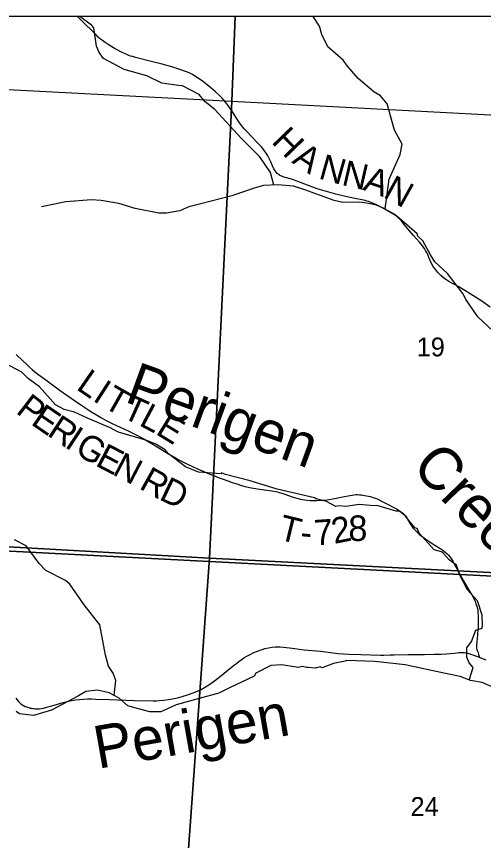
# Model space of a CAD drawing. Extents: x -2.1 to 31.9, y 6.3 to 28.3.
# Drawn here: x 1.092 to 2.128, y 25.414 to 27.244 of the extents above; entities that cross this region are included whole.
import ezdxf

# ---------------------------------------------------------------- set-up
doc = ezdxf.new("R2010")
doc.units = 0
for name, color, linetype in [('Default', 7, 'Continuous'), ('GM_X_County_Road', 7, 'Continuous'), ('GM_X_County_Road_Text', 7, 'Continuous'), ('GM_X_Minor_River', 7, 'Continuous'), ('GM_X_Minor_River_Text', 7, 'Continuous'), ('GM_X_Section', 7, 'Continuous'), ('GM_X_Section_Text', 7, 'Continuous'), ('GM_X_State_Route', 7, 'Continuous'), ('GM_X_Township_Road', 7, 'Continuous'), ('GM_X_Township_Road_Text', 7, 'Continuous'), ('SH_Cut_Line', 7, 'Continuous')]:
    doc.layers.add(name, color=color, linetype=linetype)

msp = doc.modelspace()

# ---------------------------------------------------------------- linework, layer by layer
at = {"layer": 'Default'}
msp.add_lwpolyline([(4.7331, 27.244), (0.0344, 27.244), (0.0344, 26.1105), (0.4641, 26.0883), (2.0757, 26.0047), (2.8034, 25.9683), (3.0763, 25.9555), (3.8625, 25.9158)], dxfattribs=at)
for points in [[(1.5768, 27.244), (0.5541, 27.244), (0.5464, 27.109), (1.5695, 27.0562)], [(2.6242, 27.244), (1.5768, 27.244), (1.5695, 27.0562), (2.6051, 27.0012), (2.6077, 27.001)], [(0.0344, 26.1105), (0.0344, 20.444), (3.7533, 20.444), (3.8489, 20.5389), (3.9894, 20.6326), (4.16, 20.7203), (4.2895, 20.7662), (4.3023, 20.7658), (4.3091, 20.8714), (4.3751, 21.8979), (4.4168, 22.5238), (4.4383, 22.8067), (4.4651, 23.2405), (4.4901, 23.6442), (4.5473, 24.5954), (4.5667, 24.9084), (4.6032, 25.4816), (4.6286, 25.8765), (3.8625, 25.9158), (3.0763, 25.9555), (2.8034, 25.9683), (2.0757, 26.0047), (0.4641, 26.0883)]]:
    msp.add_lwpolyline(points, close=True, dxfattribs=at)
at = {"layer": 'GM_X_County_Road'}
msp.add_lwpolyline([(2.1421, 26.5987), (2.1238, 26.6116), (2.1036, 26.6247), (2.0864, 26.6358), (2.079, 26.6401), (2.0725, 26.6437), (2.0659, 26.6472), (2.057, 26.6517), (2.0505, 26.6555), (2.0443, 26.6598), (2.0387, 26.664), (2.0333, 26.6686), (2.0294, 26.6723), (2.0262, 26.6756), (2.0217, 26.6812), (2.0185, 26.6857), (2.0163, 26.6888), (2.0125, 26.6953), (2.0093, 26.702), (2.0064, 26.709), (2.0038, 26.7153), (2.0011, 26.7208), (1.9989, 26.7246), (1.9964, 26.7286), (1.9937, 26.7324), (1.9898, 26.7373), (1.9854, 26.7425), (1.9722, 26.7578), (1.9554, 26.7779), (1.9494, 26.7854), (1.9448, 26.7909), (1.9394, 26.7963), (1.9336, 26.8014), (1.9293, 26.805), (1.9244, 26.808), (1.9176, 26.8119), (1.909, 26.8162), (1.8973, 26.8222), (1.8875, 26.8269), (1.8797, 26.8302), (1.8728, 26.8328), (1.8692, 26.834), (1.8653, 26.835), (1.8579, 26.8368), (1.8426, 26.8399), (1.8218, 26.8442), (1.8001, 26.8496), (1.7797, 26.855), (1.7688, 26.8583), (1.7586, 26.8615), (1.7371, 26.8696), (1.7162, 26.8778), (1.7088, 26.8804), (1.7019, 26.8826), (1.6879, 26.8865), (1.6831, 26.8882), (1.6785, 26.89), (1.6762, 26.8912), (1.6741, 26.8924), (1.6722, 26.8938), (1.6703, 26.8955), (1.6678, 26.8981), (1.6653, 26.9015), (1.6627, 26.9058), (1.6595, 26.9125), (1.6556, 26.921), (1.6515, 26.9299), (1.6492, 26.9345), (1.6469, 26.9384), (1.6441, 26.9427), (1.6415, 26.9464), (1.6384, 26.9505), (1.6353, 26.9543), (1.6275, 26.9628), (1.6148, 26.9758), (1.6044, 26.987), (1.5972, 26.9948), (1.592, 27.001), (1.5867, 27.0079), (1.5796, 27.0182), (1.5706, 27.0324), (1.5643, 27.042), (1.5594, 27.0491), (1.5557, 27.0538), (1.552, 27.058), (1.5479, 27.0624), (1.5412, 27.069), (1.5334, 27.0764), (1.5232, 27.0852), (1.5109, 27.0951), (1.5014, 27.1024), (1.493, 27.1081), (1.4874, 27.1117), (1.4824, 27.1148), (1.4763, 27.1178), (1.4709, 27.1202), (1.4646, 27.1229), (1.4585, 27.1251), (1.4519, 27.1273), (1.4361, 27.1321), (1.4149, 27.1381), (1.3934, 27.1435), (1.3559, 27.153), (1.3492, 27.1548), (1.345, 27.1561), (1.3411, 27.1575), (1.3369, 27.1592), (1.3326, 27.161), (1.3236, 27.1654), (1.317, 27.1688), (1.311, 27.1722), (1.3035, 27.1768), (1.2951, 27.1821), (1.2889, 27.1862), (1.2827, 27.1904), (1.2783, 27.1938), (1.2734, 27.1981), (1.2679, 27.2036), (1.2598, 27.2119), (1.2438, 27.2275), (1.2284, 27.2422), (1.2266, 27.244)], dxfattribs=at)
at = {"layer": 'GM_X_Minor_River'}
for points in [[(1.6629, 26.8693), (1.6555, 26.8976), (1.6316, 26.9326), (1.5905, 26.9737), (1.5319, 27.0375), (1.5105, 27.0545), (1.497, 27.0709), (1.4602, 27.0899), (1.4515, 27.0906), (1.4143, 27.096), (1.3811, 27.1122), (1.3305, 27.126), (1.2851, 27.1506), (1.2753, 27.1638), (1.2697, 27.1777), (1.2634, 27.2185), (1.2582, 27.2244), (1.2327, 27.244)], [(1.9093, 26.8167), (1.9185, 26.8829), (1.9424, 26.9372), (1.9469, 26.9606), (1.9305, 26.9919), (1.9141, 27.0497), (1.8995, 27.0681), (1.8847, 27.0769), (1.8493, 27.1065), (1.8263, 27.1338), (1.8165, 27.147), (1.7826, 27.1766), (1.7694, 27.2036), (1.7639, 27.2224), (1.7502, 27.244)], [(2.1487, 26.5451), (2.115, 26.5774), (2.0889, 26.6146), (2.082, 26.629), (2.0476, 26.673), (2.0196, 26.6992), (2.0101, 26.7147), (1.9927, 26.7459), (1.9817, 26.7565), (1.9806, 26.7614), (1.9409, 26.7963), (1.9363, 26.7997), (1.9049, 26.8186), (1.8902, 26.825), (1.8724, 26.8284), (1.8535, 26.8314), (1.8153, 26.8306), (1.7964, 26.8355), (1.7314, 26.8589), (1.706, 26.8672), (1.6713, 26.8705), (1.6395, 26.8685), (1.6187, 26.8628), (1.5696, 26.8459), (1.5004, 26.8278)], [(1.5006, 26.8279), (1.477, 26.8221), (1.4744, 26.8214), (1.4543, 26.8122), (1.4249, 26.8076), (1.4075, 26.8071), (1.3549, 26.8173), (1.319, 26.8286), (1.2797, 26.8353), (1.2581, 26.8368), (1.2011, 26.8321), (1.1474, 26.8213)], [(2.0958, 25.7706), (2.1044, 25.7985), (2.0957, 25.8087), (2.0904, 25.8217), (2.0908, 25.8418), (2.1006, 25.8559), (2.1108, 25.881), (2.1247, 25.886), (2.1251, 25.8924), (2.1247, 25.9145), (2.1141, 25.9464), (2.0922, 25.971), (2.0747, 26.0033), (2.0675, 26.0253), (2.0513, 26.0375), (2.038, 26.0522), (2.0342, 26.0553), (2.0184, 26.0594), (1.9847, 26.097), (1.9805, 26.1068), (1.9752, 26.1087), (1.954, 26.1353), (1.9412, 26.1455), (1.9336, 26.1459), (1.8939, 26.1572), (1.8761, 26.1583), (1.8515, 26.1605), (1.8221, 26.1562), (1.8066, 26.1573), (1.7998, 26.1558), (1.7793, 26.1668), (1.7563, 26.1732), (1.7525, 26.1751), (1.6697, 26.1946), (1.6103, 26.2127), (1.5551, 26.227), (1.5468, 26.2304), (1.546, 26.2282), (1.4958, 26.2322), (1.467, 26.2443), (1.4288, 26.2731), (1.422, 26.2818), (1.4012, 26.2943), (1.3808, 26.3023), (1.3184, 26.3207), (1.3048, 26.3275), (1.3033, 26.3294), (1.2496, 26.3521), (1.2204, 26.3653), (1.1977, 26.3714), (1.1785, 26.382), (1.1433, 26.4218), (1.1179, 26.4404), (1.1035, 26.454), (1.0544, 26.4801)], [(1.3088, 25.7363), (1.3122, 25.7695), (1.3067, 25.7856), (1.2962, 25.8011), (1.2894, 25.8256), (1.2771, 25.8932), (1.2421, 25.9376), (1.2106, 25.9834), (1.2003, 25.9918), (1.1571, 26.0136), (1.1425, 26.0297), (1.1138, 26.0686), (1.0877, 26.0819)], [(1.8244, 25.8142), (1.8209, 25.8126), (1.7948, 25.8072), (1.7699, 25.7977), (1.765, 25.7999), (1.754, 25.7973), (1.7385, 25.7987), (1.7347, 25.7987), (1.7264, 25.8006), (1.7166, 25.7987), (1.6807, 25.8043), (1.6557, 25.8031), (1.6225, 25.7855), (1.6191, 25.7794), (1.5643, 25.7534), (1.5409, 25.7412), (1.497, 25.7293), (1.446, 25.7155), (1.4124, 25.7002), (1.409, 25.7002), (1.3878, 25.7002), (1.3628, 25.7066), (1.3386, 25.7134), (1.3193, 25.7304), (1.2978, 25.7421), (1.2717, 25.7482), (1.246, 25.7454), (1.2294, 25.7359), (1.1693, 25.7038), (1.13, 25.6919), (1.099, 25.6957), (1.0914, 25.701)], [(2.1479, 25.7549), (2.1249, 25.7651), (2.0984, 25.7696), (2.0761, 25.7783), (2.0436, 25.7854), (1.954, 25.8046), (1.8863, 25.8116), (1.8244, 25.8142)]]:
    msp.add_lwpolyline(points, dxfattribs=at)
at = {"layer": 'GM_X_Section'}
for points in [[(0.5464, 27.109), (1.5695, 27.0562), (1.5197, 26.0415), (0.4693, 26.1002)], [(1.5695, 27.0562), (2.6051, 27.0012), (2.5466, 25.9887), (1.5197, 26.0415)], [(0.4693, 26.1002), (1.5197, 26.0415), (1.4457, 25.016), (0.4184, 25.0658)], [(1.5197, 26.0415), (2.5466, 25.9887), (2.4786, 24.9709), (1.4457, 25.016)]]:
    msp.add_lwpolyline(points, close=True, dxfattribs=at)
at = {"layer": 'GM_X_State_Route'}
msp.add_lwpolyline([(1.0907, 25.73), (1.0933, 25.7267), (1.0963, 25.7233), (1.099, 25.7205), (1.1019, 25.7178), (1.1045, 25.7159), (1.1072, 25.7143), (1.1115, 25.7121), (1.1141, 25.711), (1.1166, 25.7102), (1.1195, 25.7093), (1.1225, 25.7085), (1.1253, 25.7078), (1.1282, 25.7074), (1.1307, 25.7071), (1.1334, 25.7069), (1.1359, 25.7068), (1.1384, 25.7068), (1.1429, 25.707), (1.1476, 25.7075), (1.1519, 25.7082), (1.1565, 25.7093), (1.1671, 25.7123), (1.1806, 25.7166), (1.1924, 25.7201), (1.2046, 25.7232), (1.2136, 25.7251), (1.2227, 25.7266), (1.232, 25.7277), (1.2408, 25.7283), (1.2491, 25.7286), (1.2582, 25.7287), (1.2681, 25.7284), (1.2973, 25.7275), (1.3534, 25.7255), (1.3952, 25.7245), (1.4023, 25.7246), (1.409, 25.7249), (1.4183, 25.7256), (1.4288, 25.7271), (1.438, 25.7287), (1.449, 25.7312), (1.4592, 25.734), (1.4711, 25.7375), (1.4841, 25.742), (1.4933, 25.7459), (1.5012, 25.7498), (1.5088, 25.7541), (1.5182, 25.7601), (1.5279, 25.7669), (1.5404, 25.7762), (1.5727, 25.8019), (1.5803, 25.808), (1.5853, 25.8119), (1.5903, 25.8157), (1.5962, 25.8196), (1.6026, 25.8234), (1.6102, 25.8275), (1.6185, 25.8316), (1.6265, 25.835), (1.6346, 25.838), (1.6423, 25.8403), (1.6507, 25.8424), (1.6592, 25.8439), (1.6659, 25.8446), (1.6702, 25.8447), (1.6763, 25.8446), (1.6843, 25.8439), (1.6972, 25.8421), (1.7089, 25.8405), (1.719, 25.8392), (1.7302, 25.838), (1.7659, 25.8348), (1.8052, 25.8297), (1.8169, 25.8286), (1.8291, 25.828), (1.8555, 25.827), (1.8992, 25.8257), (1.9064, 25.8257), (1.9208, 25.8264), (1.9253, 25.8267), (1.9293, 25.8269), (1.9607, 25.8274), (1.9966, 25.8275), (2.0178, 25.8278), (2.0329, 25.8284), (2.0454, 25.829), (2.0636, 25.8305), (2.0726, 25.8315), (2.0775, 25.8318), (2.0812, 25.8317), (2.0845, 25.8316), (2.0878, 25.8312), (2.0907, 25.8308), (2.0947, 25.8298), (2.099, 25.8284), (2.104, 25.8268), (2.118, 25.8211), (2.1268, 25.8176), (2.1324, 25.8157)], dxfattribs=at)
at = {"layer": 'GM_X_Township_Road'}
for points in [[(1.0916, 26.4937), (1.106, 26.4794), (1.1131, 26.4726), (1.1202, 26.4662), (1.1267, 26.4604), (1.1328, 26.4552), (1.1415, 26.4484), (1.1518, 26.4407), (1.1629, 26.4324), (1.1746, 26.4236), (1.1864, 26.4148), (1.2035, 26.4031), (1.2227, 26.3899), (1.2416, 26.3773), (1.2525, 26.3699), (1.2607, 26.3646), (1.2695, 26.3592), (1.2804, 26.3527), (1.2912, 26.3467), (1.304, 26.3402), (1.3135, 26.3357), (1.3393, 26.3239), (1.3573, 26.3153), (1.3732, 26.3068), (1.3906, 26.2966), (1.4079, 26.2862), (1.4253, 26.2751), (1.4344, 26.2697), (1.4424, 26.2651), (1.4506, 26.2605), (1.4607, 26.2553), (1.4709, 26.2502), (1.4825, 26.2446), (1.4947, 26.2391), (1.5074, 26.2336), (1.521, 26.228), (1.5313, 26.2237), (1.5416, 26.2196), (1.5504, 26.2164), (1.5609, 26.2127), (1.5705, 26.2094), (1.5803, 26.206), (1.5909, 26.2025), (1.5987, 26.2003), (1.6084, 26.1981), (1.6175, 26.1964), (1.6261, 26.1951), (1.6365, 26.1938), (1.6469, 26.1925), (1.6584, 26.1908), (1.6626, 26.1902), (1.6667, 26.1893), (1.6707, 26.1883), (1.6746, 26.1872), (1.6804, 26.1854), (1.6892, 26.1824), (1.7009, 26.1783), (1.711, 26.1752), (1.7166, 26.1737), (1.7218, 26.1724), (1.7303, 26.1706), (1.7365, 26.1698), (1.7434, 26.1693), (1.75, 26.1691), (1.7579, 26.1693), (1.7674, 26.1698), (1.7759, 26.1703), (1.7852, 26.1713), (1.7938, 26.1726), (1.8042, 26.1749), (1.8153, 26.1774), (1.8312, 26.1807), (1.8361, 26.1814), (1.84, 26.1819), (1.8445, 26.1823), (1.8483, 26.1823), (1.8524, 26.1821), (1.8564, 26.1817), (1.8602, 26.1812), (1.8684, 26.1798), (1.8727, 26.1789), (1.877, 26.1778), (1.8807, 26.1768), (1.8847, 26.1755), (1.8884, 26.1741), (1.8921, 26.1726), (1.9044, 26.1665), (1.9159, 26.1604), (1.9286, 26.1539), (1.9362, 26.1497), (1.9415, 26.1463), (1.9457, 26.1435), (1.9486, 26.141), (1.9516, 26.1382), (1.9543, 26.1349), (1.9572, 26.1308), (1.9597, 26.1266), (1.9618, 26.1228), (1.965, 26.1174), (1.968, 26.1127), (1.971, 26.1088), (1.9742, 26.1051), (1.9791, 26.1001), (1.9851, 26.0947), (1.9894, 26.0911), (1.9937, 26.0876), (1.9997, 26.0832), (2.0039, 26.0802), (2.0084, 26.0772), (2.0157, 26.0725), (2.0326, 26.0621), (2.0372, 26.059), (2.0421, 26.0552), (2.0468, 26.0511), (2.0502, 26.0475), (2.053, 26.0441), (2.0558, 26.0401), (2.0593, 26.0342), (2.0656, 26.0228), (2.0689, 26.0168), (2.0721, 26.0109), (2.0759, 26.0042)], [(2.0759, 26.0042), (2.0835, 25.9908), (2.0968, 25.9678), (2.1036, 25.9564), (2.1064, 25.9511), (2.1088, 25.9455), (2.1108, 25.9401), (2.1125, 25.9348), (2.1139, 25.9295), (2.1147, 25.9251), (2.1153, 25.9203), (2.1157, 25.9132), (2.1159, 25.9056), (2.116, 25.9017), (2.116, 25.8973), (2.1158, 25.892), (2.1156, 25.8865), (2.1152, 25.8807), (2.1146, 25.8748), (2.114, 25.8692), (2.1134, 25.8637), (2.1124, 25.8546), (2.1119, 25.8489), (2.1118, 25.8464), (2.112, 25.8439), (2.1123, 25.8415), (2.113, 25.8385), (2.1138, 25.8362), (2.1155, 25.8315), (2.1168, 25.8275), (2.1174, 25.8252), (2.1176, 25.8238), (2.118, 25.8211)]]:
    msp.add_lwpolyline(points, dxfattribs=at)
at = {"layer": 'SH_Cut_Line'}
msp.add_lwpolyline([(6.8344, 20.444), (6.8344, 27.244), (0.0344, 27.244), (0.0344, 20.444)], dxfattribs=at)

# ---------------------------------------------------------------- texts
at = {"layer": 'GM_X_County_Road_Text'}
for s, rotation, p in [('H', 314.1525, (1.6555, 26.9646)), ('A', 326.6004, (1.7007, 26.9202)), ('N', 344.1566, (1.7597, 26.8848)), ('N', 347.0117, (1.8108, 26.8703)), ('A', 340.8618, (1.8579, 26.8595)), ('N', 330.9905, (1.9028, 26.8442))]:
    msp.add_text(s, height=0.0568, rotation=rotation, dxfattribs=at).set_placement(p)
at = {"layer": 'GM_X_Minor_River_Text'}
for s, height, rotation, p in [('Perigen', 0.09469, 340.0029, (1.329, 26.3893)), ('Creek', 0.0947, 314.0019, (1.9654, 26.2414)), ('Perigen', 0.0947, 10.0083, (1.2725, 25.5733))]:
    msp.add_text(s, height=height, rotation=rotation, dxfattribs=at).set_placement(p)
at = {"layer": 'GM_X_Section_Text'}
for s, p in [('19', (1.9795, 26.4893)), ('24', (1.9658, 25.4688))]:
    msp.add_text(s, height=0.04186, rotation=0, dxfattribs=at).set_placement(p)
at = {"layer": 'GM_X_Township_Road_Text'}
for s, rotation, p in [('L', 325.4107, (1.2223, 26.4175)), ('I', 327.159, (1.2589, 26.3924)), ('T', 330.5158, (1.2815, 26.3779)), ('P', 322.463, (1.0885, 26.3649)), ('T', 335.7988, (1.3235, 26.3544)), ('L', 332.1047, (1.3614, 26.3374)), ('E', 325.5485, (1.1216, 26.3396)), ('R', 326.635, (1.1576, 26.3149)), ('E', 328.4839, (1.3982, 26.318)), ('I', 326.7269, (1.1967, 26.2892)), ('G', 329.3578, (1.2186, 26.2749)), ('E', 332.4783, (1.2646, 26.2478)), ('N', 332.4428, (1.3023, 26.2281)), ('R', 330.8612, (1.3617, 26.197)), ('D', 334.4086, (1.4059, 26.1725)), ('T', 346.3411, (1.6701, 26.0831)), ('7', 3.9594, (1.7535, 26.0691)), ('2', 11.512, (1.7965, 26.0726)), ('8', 359.9349, (1.8278, 26.0793)), ('-', 354.1829, (1.7197, 26.0716))]:
    msp.add_text(s, height=0.0568, rotation=rotation, dxfattribs=at).set_placement(p)

doc.saveas('drawing.dxf')
